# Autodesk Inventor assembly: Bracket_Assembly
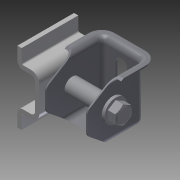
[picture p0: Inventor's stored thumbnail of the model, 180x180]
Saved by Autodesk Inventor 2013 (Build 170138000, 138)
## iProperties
Created: 2004-07
Part Number: Bracket_Assembly
Document SubType Name: Assembly
Designer: leeha
Manufacturer: Standard
Standards Organization: Custom
Mass: 823.539 g
Surface Area: 812.233 cm^2
Volume: 142.126 cm^3
Density: 5.79442 g/cm^3
Author: leeha
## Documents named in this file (7)
- C:\Users\boganb\Documents\B2 Design\Goodyear\2013 Tutorial Files\Assembly FEA 2\Bracket_Assembly.iam
- C:\Users\boganb\Documents\B2 Design\Goodyear\2013 Tutorial Files\Assembly FEA 2\Bracket.ipt
- C:\Users\boganb\Documents\B2 Design\Goodyear\2013 Tutorial Files\Assembly FEA 2\Mount.ipt
- C:\Users\boganb\Documents\B2 Design\Goodyear\2013 Tutorial Files\Assembly FEA 2\Sleeve.ipt
- C:\Users\boganb\Documents\B2 Design\Goodyear\2013 Tutorial Files\Assembly FEA 2\Bolt.ipt
- C:\Users\boganb\Documents\B2 Design\Goodyear\2013 Tutorial Files\Assembly FEA 2\Washer.ipt
- C:\Users\boganb\Documents\B2 Design\Goodyear\2013 Tutorial Files\Assembly FEA 2\Nut.ipt
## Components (8 placed, 6 different names)
1. Mount:1 — Mate:7, Mate:8, Mate:12, Angle:1
2. Bracket:1 — Mate:1, Mate:2, Mate:3, Mate:4, Mate:5, Mate:6, Mate:8, Mate:9, Angle:1
3. Sleeve:1 — Mate:1, Mate:2
4. Bolt:1 — Mate:9, Mate:10, Mate:11, Mate:13
5. Washer:1 — Mate:11, Mate:12, Mate:14
6. Washer:2 — Mate:3, Mate:4, Mate:10
7. Washer:3 — Mate:5, Mate:6, Mate:7
8. Nut:1 — Mate:13, Mate:14
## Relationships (15: Mate 14, Angle 1)
- Mate:1: Bracket:1 ↔ Sleeve:1
- Mate:2: Bracket:1 ↔ Sleeve:1
- Mate:3: Bracket:1 ↔ Washer:2
- Mate:4: Bracket:1 ↔ Washer:2
- Mate:5: Bracket:1 ↔ Washer:3
- Mate:6: Bracket:1 ↔ Washer:3
- Mate:7: Mount:1 ↔ Washer:3
- Mate:8: Mount:1 ↔ Bracket:1
- Mate:9: Bracket:1 ↔ Bolt:1
- Mate:10: Bolt:1 ↔ Washer:2
- Mate:11: Bolt:1 ↔ Washer:1
- Mate:12: Mount:1 ↔ Washer:1
- Mate:13: Bolt:1 ↔ Nut:1
- Mate:14: Washer:1 ↔ Nut:1
- Angle:1: Mount:1 ↔ Bracket:1
